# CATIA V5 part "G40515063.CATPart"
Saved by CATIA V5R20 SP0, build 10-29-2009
Part number: G40515063
Revision: 7
Definition: design
Nomenclature: G40515063
Source: made
Description: NOT SPECIFIED
Bounding box of the stored display mesh (mm): x -31.5 to 31.5, y -10 to 10, z -15 to 0
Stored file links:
  C:\Users\Raffaele\Desktop\3D X SITO CF\BOLEX\29-GUIDE STRIP REF 405\G40515063.CATPart
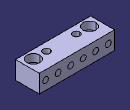
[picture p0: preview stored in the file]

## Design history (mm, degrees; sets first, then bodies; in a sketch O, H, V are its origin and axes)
Body1 "MANIFOLD_SOLID_BREP #1750" (main body)
  Solid1: solid without history
Body2 "MANIFOLD_SOLID_BREP #1888"
  Solid2: solid without history
Body3 "MANIFOLD_SOLID_BREP #2000"
  Solid3: solid without history
Body4 "MANIFOLD_SOLID_BREP #2112"
  Solid4: solid without history
Body5 "MANIFOLD_SOLID_BREP #2224"
  Solid5: solid without history
Body6 "MANIFOLD_SOLID_BREP #2336"
  Solid6: solid without history
Body7 "MANIFOLD_SOLID_BREP #2448"
  Solid7: solid without history
Body8 "MANIFOLD_SOLID_BREP #2586"
  Solid8: solid without history
Body9 "MANIFOLD_SOLID_BREP #2724"
  Solid9: solid without history
Body10 "MANIFOLD_SOLID_BREP #2862"
  Solid10: solid without history
Body11 "MANIFOLD_SOLID_BREP #3000"
  Solid11: solid without history
Body12 "MANIFOLD_SOLID_BREP #3112"
  Solid12: solid without history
